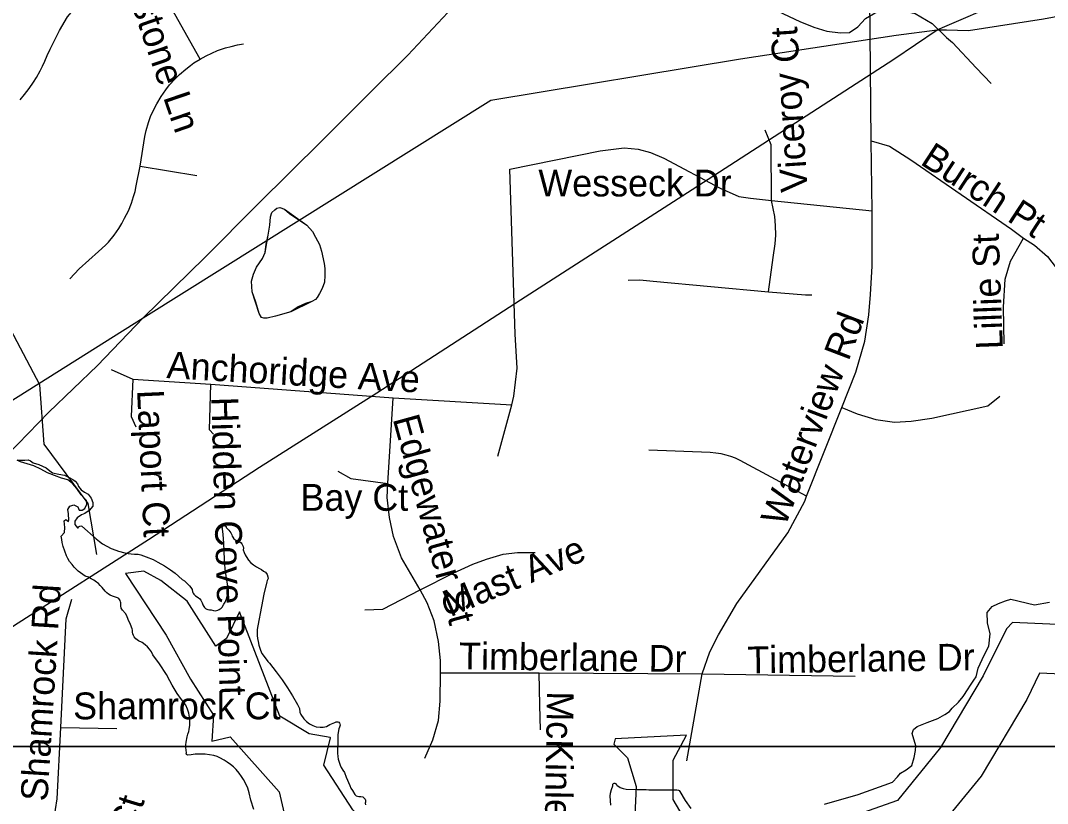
# Model space of a CAD drawing. Extents: x 1662474 to 1856135, y 779280 to 917889.
# Drawn here: x 1701087 to 1704721, y 826386 to 829158 of the extents above; entities that cross this region are included whole.
import ezdxf

# ---------------------------------------------------------------- set-up
doc = ezdxf.new("R2010")
doc.units = 0
for name, color, linetype in [('Exist Hydrographic Lake Shore', 7, 'Continuous'), ('Exist Hydrographic Misc Water Feature', 7, 'Continuous'), ('Exist Road Non-System Type 51', 7, 'Continuous'), ('Exist Road Non-System Type 51 Label', 7, 'Continuous'), ('Exist Utilities Electrical Transmission Line', 7, 'Continuous'), ('Map Preparation Inset Cut Line', 7, 'Continuous'), ('Old_Level_44', 7, 'Continuous')]:
    doc.layers.add(name, color=color, linetype=linetype)

msp = doc.modelspace()

# ---------------------------------------------------------------- linework, layer by layer
at = {"layer": 'Exist Hydrographic Lake Shore'}
for points in [[(1701499.4, 826965.1), (1701494.1, 826969.6), (1701489.2, 826975.8), (1701486.2, 826980.8), (1701484.2, 826987.1), (1701483.1, 826992.6), (1701482.9, 826999.4), (1701481.4, 827004.9), (1701476.1, 827019.4), (1701467.6, 827037.5), (1701462.6, 827050.6), (1701458.2, 827058.8), (1701447.2, 827070.8), (1701443.2, 827077.7), (1701441.1, 827086.6), (1701441.1, 827096.3), (1701440.9, 827100), (1701439.1, 827104.9), (1701437, 827108.6), (1701433.9, 827111.8), (1701429.6, 827114.7), (1701426.2, 827116), (1701419.4, 827117.3), (1701412, 827119.9), (1701404.1, 827123.6), (1701397.6, 827127.8), (1701391.5, 827132.2), (1701386, 827137.5), (1701375.8, 827150.6), (1701368.5, 827158.5), (1701362.1, 827164.6), (1701355.6, 827170.1), (1701346.4, 827176.6), (1701337, 827182.1), (1701327.2, 827187.1), (1701315.5, 827191.6), (1701307.2, 827196.8), (1701291, 827208.9), (1701276.6, 827222.8), (1701269, 827231.8), (1701260.4, 827243.2), (1701254.2, 827253), (1701249, 827263.2), (1701237, 827296.1), (1701234.1, 827309.7), (1701232.8, 827320.9), (1701230.1, 827333.1), (1701241.8, 827345.6), (1701242.8, 827363.5), (1701240.6, 827386.9), (1701247, 827391.3), (1701256.4, 827384.5), (1701257.5, 827388.7), (1701256.4, 827411.5), (1701253.8, 827427), (1701260.6, 827439.1), (1701274.8, 827443), (1701289.5, 827437), (1701294.5, 827424.6), (1701305, 827424.4), (1701314.1, 827430.9), (1701320.8, 827446.2), (1701319.4, 827458.8), (1701300.8, 827479), (1701285.2, 827501), (1701271.1, 827518.1), (1701253.8, 827531.8), (1701231.5, 827538.3), (1701181.4, 827557.4), (1701158, 827570.1), (1701134.1, 827581.9), (1701086.9, 827596.3), (1701075, 827602.1), (1701101.5, 827602.1), (1701113.1, 827603.1), (1701122.2, 827598.9), (1701131.5, 827592.1), (1701151.1, 827586.1), (1701176.9, 827574.5), (1701190.2, 827563.8), (1701200, 827556.9), (1701222.2, 827551.9), (1701242, 827549.1), (1701256.4, 827541.9), (1701271.1, 827533.8), (1701280, 827526.8), (1701287.9, 827517.6), (1701291.9, 827508.6), (1701301, 827497.1), (1701312.9, 827488.9), (1701326, 827481.1), (1701336.1, 827466.6), (1701342, 827452.2), (1701342, 827438.6), (1701329.9, 827423.9), (1701314.1, 827412.6), (1701302.4, 827408.6), (1701286.6, 827398.1), (1701279, 827385.8), (1701279, 827373.8)], [(1701279, 827373.8), (1701287.9, 827362.2), (1701290.2, 827362.7), (1701292.1, 827365.9), (1701293.9, 827367.4), (1701296.2, 827368.5), (1701300, 827368.8), (1701303.6, 827367.7), (1701354, 827323.1), (1701366.1, 827313.4), (1701376.6, 827305.8), (1701407.2, 827288.9), (1701410.8, 827287.4), (1701432.8, 827279.2), (1701455.4, 827273.2), (1701466.9, 827271.4), (1701478.4, 827269.8), (1701490.2, 827269), (1701502.6, 827269), (1701512, 827266.1), (1701530.9, 827259.6), (1701555.4, 827249.6), (1701572.9, 827240.9), (1701596, 827227.8), (1701617.8, 827213.4), (1701633.8, 827201.3), (1701658.5, 827179.8), (1701666.9, 827174.2), (1701675.8, 827164.8), (1701684.8, 827156.7), (1701689.5, 827150.9), (1701693.4, 827144.3), (1701695.2, 827135.9), (1701697.4, 827130.9), (1701699.8, 827127.2), (1701705.2, 827122), (1701715.4, 827115.4), (1701720.6, 827110.8), (1701724.1, 827106.6), (1701727, 827101.8), (1701729.1, 827096.8), (1701731.5, 827089.2), (1701734.9, 827083.2), (1701737.5, 827080), (1701741.1, 827076.9), (1701745.6, 827074), (1701749.2, 827072.7), (1701755.4, 827071.4), (1701761.6, 827071.4), (1701770, 827069), (1701776.4, 827068.8), (1701785, 827070.3), (1701790, 827072.7), (1701796.8, 827077.9), (1701799.8, 827081.1), (1701806.5, 827091.6), (1701810.8, 827098.9), (1701815.8, 827111), (1701819.4, 827125.4), (1701821, 827137), (1701820.6, 827148.5), (1701819.9, 827156.9), (1701815.1, 827184.2), (1701811, 827217.1), (1701808.9, 827249.8), (1701806.5, 827307.6), (1701803.9, 827338.8), (1701801.5, 827358.5), (1701800.2, 827362.4), (1701800.8, 827365.3), (1701801.5, 827367.2), (1701803.9, 827369.2), (1701807.9, 827370.3), (1701811, 827369.5), (1701813.9, 827366.9), (1701814.9, 827362.9), (1701823.6, 827353.8), (1701830.6, 827344.3), (1701834.6, 827337.2), (1701835.9, 827332.8), (1701837.5, 827329.6), (1701841.6, 827323.6), (1701844.6, 827321.2), (1701848.5, 827318.9), (1701852.8, 827317.1), (1701856.6, 827316), (1701862.4, 827313.1), (1701867.1, 827309.2), (1701870.2, 827305.2), (1701872.6, 827300.8), (1701874.5, 827296.1), (1701875.2, 827289.8), (1701874.8, 827283.7), (1701877.9, 827275.1), (1701881.6, 827266.6), (1701885.2, 827260.3), (1701893.6, 827248.2), (1701902.2, 827238.8), (1701910.5, 827231.4), (1701921.2, 827224.1)], [(1701921.2, 827224.1), (1701932.5, 827218.4), (1701939.4, 827214.9), (1701946.6, 827209.2), (1701954, 827204.9), (1701959.2, 827197.1), (1701961.9, 827188.2), (1701962.4, 827182.9), (1701959, 827176.1), (1701958.2, 827171.1), (1701948.2, 827127), (1701939.4, 827083.4), (1701926.5, 827015.4), (1701924.6, 827002.3), (1701924.1, 826991.8), (1701924.4, 826981.1), (1701925.4, 826970.6), (1701927.2, 826960.1), (1701930.1, 826947.2), (1701936.1, 826928.6), (1701941.1, 826917.8), (1701955.6, 826897.1), (1701962.1, 826888.9), (1701968.2, 826882.7), (1701991.8, 826852.5), (1702012, 826824.6), (1702031.5, 826796.1), (1702049.5, 826766.9), (1702066.9, 826737), (1702073.8, 826722.8), (1702075, 826709.7), (1702078.4, 826701.3), (1702088.9, 826686.1), (1702098.1, 826676.4), (1702108.9, 826668.2), (1702120.6, 826662.2), (1702133.2, 826658.2), (1702146.6, 826656.7), (1702157.4, 826656.9), (1702169, 826659.1), (1702181.6, 826665.6), (1702199.1, 826672.7), (1702203.9, 826675.3), (1702206.2, 826675.6), (1702209.6, 826675.1), (1702213.1, 826673.8), (1702215.8, 826671.1), (1702217.2, 826668.2), (1702218, 826663.5), (1702217.2, 826660.1), (1702215.4, 826656.9), (1702213.6, 826650.9), (1702210.1, 826630.9), (1702209.1, 826613.4), (1702209.9, 826595.8), (1702208.4, 826584.5), (1702207.9, 826575.3), (1702208.1, 826564), (1702209.4, 826552.5), (1702211, 826543.6), (1702214.1, 826532.6), (1702218, 826522.1), (1702221.8, 826513.6), (1702227.2, 826503.7), (1702232.8, 826495.5), (1702239, 826479.8), (1702251.9, 826450.4), (1702255, 826440.9), (1702261.9, 826432.6), (1702270.2, 826418.1), (1702274.8, 826413.9), (1702279.2, 826411.8), (1702283.9, 826411), (1702291.2, 826411.2), (1702297.6, 826409.7), (1702301.8, 826406.8), (1702305.8, 826401.8), (1702307.2, 826398.4), (1702307.9, 826394.5), (1702307.9, 826390.8), (1702306.8, 826386.9), (1702307.2, 826381.9)], [(1704190.2, 826480.1), (1704201.2, 826494.2), (1704221.4, 826505.8), (1704241.6, 826520.8), (1704250, 826549.6), (1704254.5, 826574.2), (1704255.2, 826590), (1704241.9, 826634.4), (1704247.4, 826648), (1704259.8, 826658.5), (1704294.9, 826672.7), (1704332.8, 826687.1), (1704357.9, 826701.1), (1704374.1, 826712.1), (1704383.6, 826724.1), (1704406.5, 826744.6), (1704422.8, 826765.1), (1704440.6, 826792.1), (1704446.1, 826802.1), (1704460.2, 826822.3), (1704468.4, 826834.9), (1704476.5, 826865.9), (1704496.8, 826911.2), (1704514.1, 826943.8), (1704518.2, 826986.3), (1704509.1, 827025.9), (1704507.8, 827062.4), (1704525.1, 827084.2), (1704547.6, 827094.8), (1704572.9, 827103.9), (1704591, 827109.2), (1704675.5, 827090), (1704728.2, 827099.2)], [(1701536.1, 826940.9), (1701528, 826948.2), (1701516.5, 826956.4), (1701504.1, 826962.2), (1701499.4, 826965.1)], [(1701912.2, 826364.8), (1701902, 826398.4), (1701896, 826423.9), (1701890.8, 826440.1), (1701884, 826455.9), (1701876.1, 826470.9), (1701868.8, 826482.4), (1701860.6, 826493.4), (1701849.5, 826506.3), (1701839.9, 826516), (1701829.4, 826524.7), (1701818.4, 826533.1), (1701806.8, 826540.1), (1701791.9, 826548.2), (1701782.4, 826552.5), (1701770.5, 826556.7), (1701739.9, 826560.4), (1701705, 826560.4), (1701690.2, 826559.1), (1701678.8, 826557.2), (1701676.6, 826558), (1701674.2, 826560.1), (1701673.1, 826563.2), (1701673.8, 826565.9), (1701671.9, 826584.5), (1701671.9, 826594.2), (1701672.6, 826603.9), (1701676.1, 826622.8), (1701678.8, 826632), (1701682.1, 826641.2), (1701683.6, 826648.2), (1701685.2, 826663), (1701685.5, 826675.1), (1701684.5, 826692.1), (1701681.9, 826706.6), (1701677.4, 826720.4), (1701671.4, 826734.9), (1701655.9, 826754.6), (1701641.4, 826775.1), (1701623, 826804.9), (1701614.6, 826820.7), (1701603.4, 826843.3), (1701578.1, 826880.3), (1701554.8, 826912.1), (1701549.5, 826923.3), (1701543.2, 826932.5), (1701536.1, 826940.9)], [(1703175.5, 826380.6), (1703174, 826412.6), (1703174.5, 826422.8), (1703177.6, 826435.4), (1703183.1, 826448.8), (1703182.4, 826451.9), (1703182.9, 826454.1), (1703185, 826456.7), (1703188.1, 826458), (1703190.2, 826458), (1703192.2, 826456.9), (1703193.9, 826455.6), (1703196, 826452.2), (1703198.1, 826450.1), (1703204.1, 826445.9), (1703209.4, 826442.8), (1703219.1, 826438.8), (1703230.4, 826436.5), (1703269, 826435.7), (1703301, 826436.2), (1703310.1, 826434.9), (1703409.9, 826434.9), (1703414.9, 826433.3), (1703417.2, 826431.8), (1703420.1, 826428.9), (1703439.2, 826397.1), (1703459.2, 826368.2)], [(1703932.2, 826384.2), (1704050.9, 826417.8), (1704172.9, 826461.7), (1704190.2, 826480.1)]]:
    msp.add_lwpolyline(points, dxfattribs=at)
at = {"layer": 'Exist Hydrographic Misc Water Feature'}
for points in [[(1701357, 827267.3), (1701326.1, 827448.5), (1701170, 827658.5), (1701155, 827868.8), (1700959, 828237.2), (1700169, 829178.9), (1700005, 829454.6), (1699824.4, 829654.8)], [(1703219.3, 829651.9), (1703249.2, 829638.2), (1703292.6, 829605.3), (1703373.7, 829540.4), (1703532.2, 829400.2), (1703555.5, 829357.9), (1703590.9, 829311.2), (1703665.9, 829244), (1703767.3, 829191), (1703844.9, 829154.1), (1703894.5, 829135.1), (1703940.2, 829120.2), (1703988.3, 829114.3), (1704020.3, 829115.3), (1704050.5, 829135.2), (1704076.9, 829165), (1704119.4, 829190.5), (1704171.5, 829201.7), (1704253.2, 829182.8), (1704312.7, 829147.9), (1704363.5, 829098.5)], [(1704363.5, 829098.5), (1704385.2, 829080.8), (1704469, 828990.5), (1704522.5, 828935.2)], [(1702099.4, 828433.1), (1702119.7, 828411.3), (1702130.8, 828390.6), (1702144.5, 828364.9), (1702151.7, 828341), (1702161.4, 828298), (1702163.3, 828280), (1702163.1, 828255.4), (1702162.6, 828231.6), (1702154.3, 828209.6), (1702144.2, 828191.7), (1702136.4, 828177.9), (1702130, 828169.9), (1702117.7, 828163.6), (1702095.7, 828156.6), (1702069.6, 828144.8), (1702043.3, 828127.3), (1701989.1, 828112), (1701958.9, 828104.4), (1701947.8, 828103.8), (1701939.1, 828106.4), (1701931.2, 828120.6), (1701919.9, 828161), (1701906.3, 828197.4), (1701904.5, 828235.2), (1701910.7, 828259.7), (1701921.4, 828284.9), (1701942.5, 828315.6), (1701951.9, 828336.8), (1701956.4, 828366.3), (1701962.9, 828398.1), (1701969.3, 828434), (1701971.8, 828462.8), (1701976.4, 828478.2), (1701986, 828487.9), (1701994.2, 828493.5), (1702004.3, 828495.8), (1702020.8, 828490.4), (1702037.9, 828475.4), (1702099.4, 828433.1)], [(1702099.4, 828433.1), (1702119.7, 828411.3), (1702130.8, 828390.6), (1702144.5, 828364.9), (1702151.7, 828341), (1702161.4, 828298), (1702163.3, 828280), (1702163.1, 828255.4), (1702162.6, 828231.6), (1702154.3, 828209.6), (1702144.2, 828191.7), (1702136.4, 828177.9), (1702130, 828169.9), (1702117.7, 828163.6), (1702043.3, 828127.3), (1701989.1, 828112), (1701958.9, 828104.4), (1701947.8, 828103.8), (1701939.1, 828106.4), (1701931.2, 828120.6), (1701906.3, 828197.4), (1701904.5, 828235.2), (1701910.7, 828259.7), (1701921.4, 828284.9), (1701942.5, 828315.6), (1701951.9, 828336.8), (1701962.9, 828398.1), (1701969.3, 828434), (1701971.8, 828462.8), (1701976.4, 828478.2), (1701986, 828487.9), (1701994.2, 828493.5), (1702004.3, 828495.8), (1702020.8, 828490.4), (1702099.4, 828433.1)]]:
    msp.add_lwpolyline(points, dxfattribs=at)
at = {"layer": 'Exist Road Non-System Type 51'}
for p, q in [((1704096.8, 828731.9), (1704091.8, 829315.4)), ((1704100.4, 828484.2), (1704096.8, 828731.9)), ((1701510.4, 828642.2), (1701710.1, 828608.9)), ((1703744.8, 828520.4), (1704100.4, 828484.2)), ((1701407.2, 827922.2), (1701483.4, 827888.2)), ((1701483.4, 827888.2), (1701760.4, 827870.2)), ((1701760.4, 827870.2), (1702405.6, 827822.2)), ((1702386.9, 827518.6), (1702405.6, 827822.2)), ((1702405.6, 827822.2), (1702825.1, 827797.4)), ((1702775.8, 827616.2), (1702825.1, 827797.4)), ((1703868.9, 827474.5), (1703993.6, 827788.2)), ((1702573.1, 826849), (1702922.5, 826848.8)), ((1702922.5, 826848.8), (1703498.9, 826845.4)), ((1703444.8, 826537.2), (1703498.9, 826845.4)), ((1703498.9, 826845.4), (1704041.1, 826837.5)), ((1701229.4, 826655.4), (1701427, 826651.9))]:
    msp.add_line(p, q, dxfattribs=at)
for points in [[(1701722.5, 829021.2), (1701611.8, 829218.6), (1701607.2, 829228.2), (1701593.9, 829252.4), (1701586.9, 829263.9), (1701575, 829281), (1701562.4, 829297.6), (1701549.2, 829313.4), (1701539.9, 829323.2), (1701530.1, 829333), (1701514.9, 829347.2), (1701504.1, 829355.9), (1701488.1, 829368.7), (1701452.4, 829399.7)], [(1701084.8, 828876.9), (1701100.5, 828895.8), (1701117.2, 828917.8), (1701132.8, 828940.4), (1701142.8, 828956.1), (1701156.1, 828980.5), (1701164.5, 828997), (1701172.1, 829013.9), (1701180.8, 829034.6), (1701191, 829056.6), (1701213.4, 829101.2), (1701224.6, 829122.8), (1701252.6, 829171), (1701272.9, 829194.2)], [(1701722.5, 829021.2), (1701744, 829033), (1701764, 829042.4), (1701784.1, 829051.4), (1701797.4, 829056.4), (1701811.5, 829061.1), (1701832.5, 829066.4), (1701854, 829071.6), (1701875.8, 829075)], [(1701510.4, 828642.2), (1701526.1, 828747.9), (1701530.9, 828769.2), (1701539.4, 828797.6), (1701546.9, 828818), (1701555.9, 828838), (1701569, 828863.7), (1701583.9, 828888.7), (1701600.8, 828912.5), (1701613.9, 828929.9), (1701633.5, 828951.1), (1701649, 828966.6), (1701671.1, 828985.5), (1701688.4, 828999.2), (1701699.9, 829007.8), (1701722.5, 829021.2)], [(1703744.8, 828520.4), (1703743.8, 828717.5), (1703722.1, 828770.5)], [(1704096.8, 828731.9), (1704162.6, 828713.1), (1704237.4, 828664.5), (1704593.9, 828419.4), (1704636.4, 828387.1)], [(1702825.1, 827797.4), (1702832.4, 827827.8), (1702844, 827927.8), (1702836.9, 828047.7), (1702818, 828631.4), (1703138, 828696.2), (1703223.5, 828707.2), (1703273.1, 828702.6), (1703316.1, 828691.2), (1703363.4, 828670.5), (1703562.4, 828564.2), (1703628.5, 828534.9), (1703669.8, 828528.9), (1703744.8, 828520.4)], [(1701260.9, 828243.4), (1701294.5, 828279.5), (1701362.5, 828340), (1701386.9, 828362.7), (1701397.8, 828373.6), (1701417.9, 828397.9), (1701433.9, 828421.4), (1701445.6, 828439.9), (1701454.9, 828458.4), (1701468.4, 828484.4), (1701479.2, 828511.2), (1701486.8, 828534.8), (1701491.9, 828552.4), (1701496, 828572.6), (1701510.4, 828642.2)], [(1703733.5, 828198.1), (1703750, 828319.4), (1703756.9, 828367.1), (1703759.5, 828398.4), (1703758.4, 828432.5), (1703755.9, 828464.8), (1703744.8, 828520.4)], [(1703993.6, 827788.2), (1704042.6, 827913.1), (1704075.2, 828022.8), (1704089.1, 828116.2), (1704095.4, 828188.7), (1704100.4, 828288.7), (1704100.4, 828484.2)], [(1704567.6, 828014.1), (1704566.2, 828143.5), (1704571.9, 828243), (1704590.6, 828306), (1704636.4, 828387.1)], [(1704636.4, 828387.1), (1704674.9, 828363.2), (1704721.9, 828322.5), (1704809.4, 828206.8)], [(1703236.6, 828239), (1703277.9, 828239.9), (1703325.1, 828235.9), (1703733.5, 828198.1)], [(1703733.5, 828198.1), (1703864.8, 828186.9), (1703887, 828186.6)], [(1701483.4, 827888.2), (1701478.1, 827755.9), (1701494.6, 827719.4)], [(1701769.8, 827693.4), (1701755.1, 827708.9), (1701760.4, 827870.2)], [(1703993.6, 827788.2), (1704047.9, 827766.1), (1704113.5, 827745.4), (1704180.1, 827735.9), (1704238.5, 827740.1), (1704312.5, 827750.6), (1704510.4, 827794.4), (1704552.1, 827828.6)], [(1703868.9, 827474.5), (1703633, 827601), (1703617.2, 827608.4), (1703600.6, 827614.7), (1703583.9, 827619.7), (1703566.9, 827623.9), (1703547.4, 827627), (1703527.1, 827628.9), (1703310.1, 827636.7)], [(1702209.4, 827563.2), (1702255.4, 827536.9), (1702386.9, 827518.6)], [(1702501.5, 827142.5), (1702434.6, 827255.9), (1702406.8, 827330.9), (1702392.4, 827398.4), (1702383.9, 827469), (1702386.9, 827518.6)], [(1703498.9, 826845.4), (1703526.4, 826923.4), (1703556.6, 826983.4), (1703621.6, 827093.9), (1703801.8, 827344.4), (1703861.9, 827456.4), (1703868.9, 827474.5)], [(1702501.5, 827142.5), (1702617.2, 827201.5), (1702687.4, 827233.6), (1702735.9, 827251.4), (1702794.4, 827269.2), (1702845.4, 827275.2), (1702908.4, 827275)], [(1702305.1, 827071.6), (1702368.6, 827074.5), (1702501.5, 827142.5)], [(1702573.1, 826849), (1702573.1, 826892.9), (1702565.9, 826959.9), (1702550.6, 827033.2), (1702525.6, 827097.1), (1702501.5, 827142.5)], [(1701229.4, 826655.4), (1701248, 827039.6), (1701268.1, 827109.7)], [(1702517.2, 826546.2), (1702546.1, 826611.8), (1702565.9, 826679.5), (1702571.9, 826748), (1702573.1, 826849)], [(1702926.9, 826646.8), (1702924.6, 826734.4), (1702922.5, 826848.8)], [(1701191.2, 826289.8), (1701204.9, 826327), (1701216.2, 826402.6), (1701229.4, 826655.4)]]:
    msp.add_lwpolyline(points, dxfattribs=at)
at = {"layer": 'Exist Utilities Electrical Transmission Line'}
for points in [[(1704330.5, 829125.1), (1704357.7, 829137.4), (1704549.9, 829219.5), (1704987.4, 829509.1), (1705656.6, 829944.3), (1706235.2, 830322.3), (1706743.5, 830657.3), (1707181, 830946.8), (1707763.6, 831326.9), (1708303.7, 831673.4), (1708928.7, 832081.1), (1709620.3, 832536.3), (1710291.6, 832975.4), (1711027.5, 833455.9), (1711648.5, 833863.6), (1712239.1, 834253.8), (1713005.3, 834756), (1713847.9, 835307.5)], [(1704330.5, 829125.1), (1704363.9, 829125.2), (1704441.7, 829122.8), (1704707.5, 829163.8), (1705527.8, 829317.2), (1706167.7, 829434.6), (1706717.3, 829530.9), (1706941.1, 829496.5), (1707139, 829464.5), (1707886.3, 829332.6), (1708789.5, 829173.1), (1709700.6, 829009.5), (1710597.6, 828852.2), (1711504.6, 828682.4), (1712417.9, 828528.9), (1713335, 828365.2)], [(1701520.4, 828105.5), (1701738.8, 828319.2), (1701924.9, 828507.3), (1702155.5, 828734.8), (1702327.5, 828907), (1702457, 829035.6), (1702598.5, 829186.2)], [(1698412.5, 825294.6), (1698803.4, 825554.4), (1700105.2, 826390.5), (1700818.4, 826854.9), (1701078.4, 827026.1), (1701539.9, 827321.1), (1701932.7, 827576.9), (1702347.7, 827840.4), (1702855.5, 828168.9), (1703464, 828560.4), (1704177.3, 829020.8), (1704330.5, 829125.1)], [(1701520.4, 828105.5), (1702751.3, 828876.4), (1703635.2, 829022.8), (1704186.3, 829106.6), (1704330.5, 829125.1)], [(1692929.2, 823686.1), (1695261.2, 824166.9), (1701520.4, 828105.5)], [(1698412.5, 825294.6), (1699147.3, 825882.8), (1699284.5, 825997.3), (1699599.4, 826250), (1700023.5, 826605.4), (1700136.8, 826718.2), (1700328.8, 826908.2), (1700598, 827177.3), (1700966.1, 827545.4), (1701186.6, 827771.1), (1701358.5, 827937.3), (1701520.4, 828105.5)]]:
    msp.add_lwpolyline(points, dxfattribs=at)
at = {"layer": 'Map Preparation Inset Cut Line'}
for points in [[(1731035.7, 826588.1), (1668486.3, 826588.1), (1668486.3, 870408.9), (1731035.7, 870408.9)], [(1731035.7, 782767.4), (1668486.3, 782767.4), (1668486.3, 826588.1), (1731035.7, 826588.1)]]:
    msp.add_lwpolyline(points, close=True, dxfattribs=at)
at = {"layer": 'Old_Level_44'}
for points in [[(1705901.8, 829015.1), (1705894.7, 828930.6), (1705916.2, 828927.9), (1706106.2, 828756), (1706166.5, 828501.8), (1706147, 828268.2), (1706022.5, 828070.5), (1705831, 827949.4), (1705417.3, 827839.9), (1705401.3, 827859.9), (1705238.3, 827705.6), (1705164.3, 827606.9), (1705103.7, 827506.1), (1705250.5, 827304.5), (1705061.4, 827039.9), (1704848.8, 826840.7), (1704693.6, 826847.2), (1704647.9, 826754.4), (1704486.8, 826483.2), (1704294.5, 826248.3)], [(1701861.1, 827065.1), (1701815.9, 826970.7), (1701777.6, 826943.2), (1701676.4, 827102.1), (1701582.6, 827175.8), (1701523.2, 827208.2), (1701458.5, 827201), (1701602, 826981.7), (1701687.5, 826826.3), (1701769.3, 826699.2), (1701763.1, 826607.3), (1701828, 826622.5), (1702002.2, 826427.9), (1702044.3, 826243.1), (1702070.3, 826171.7), (1702153.2, 826055.6), (1702169.2, 825911.6), (1702235.9, 825791.6), (1702327.1, 825685.3), (1702414.3, 825554.6), (1702287.7, 825455.1)], [(1702964.1, 826137.9), (1702860.1, 826096.3), (1702783.8, 826011.7), (1702637.3, 826000.4), (1702530.3, 826087.9), (1702435.7, 826198.2), (1702262.2, 826363.7), (1702159.6, 826522.1), (1702183.8, 826618.7), (1702183, 826620.3), (1702107.9, 826632.8), (1702004.2, 826695), (1701861.1, 827065.1)], [(1704782.6, 827019), (1704597.5, 827026.7), (1704575.9, 827005.1), (1704493.6, 826838), (1704342.8, 826584), (1704190, 826397.4), (1704046, 826346.6)], [(1703471.4, 826272.2), (1703396.7, 826400.2), (1703396.7, 826539.1), (1703444, 826627.7), (1703190.8, 826615.7), (1703186, 826596.7), (1703235.2, 826547.7), (1703265.5, 826446.4), (1703255.9, 826243.3)]]:
    msp.add_lwpolyline(points, dxfattribs=at)

# ---------------------------------------------------------------- texts
at = {"layer": 'Exist Road Non-System Type 51 Label'}
for s, rotation, p in [('Netherstone Ln', 288.8424, (1701355.6, 829575.3)), ('Viceroy Ct', 93.6893, (1703872.7, 828553.2)), ('Burch Pt', 326.8433, (1704267.1, 828651.6)), ('Lillie St', 92.1138, (1704563.7, 827995.5)), ('Waterview Rd', 69.0979, (1703792.7, 827362.9)), ('Anchoridge Ave', 356.6963, (1701601.9, 827892.4)), ('Laport Ct', 272.6011, (1701499, 827849.3)), ('Hidden Cove Point', 271.6356, (1701761.6, 827824.9)), ('Edgewater St', 285.4138, (1702403.1, 827748)), ('Mast Ave', 22.8453, (1702607.2, 827045.3)), ('Shamrock Rd', 86.4257, (1701181.5, 826392.1)), ('Timberlane Dr', 359.2853, (1702638.4, 826861.3)), ('Timberlane Dr', 0.7981, (1703659.3, 826846.7)), ('McKinley St', 269.0765, (1702950, 826784)), ('Northshore Ct', 73.28, (1701299.1, 825639.9))]:
    msp.add_text(s, height=95, rotation=rotation, dxfattribs=at).set_placement(p)
for s, p in [('Wesseck Dr', (1702919.2, 828535.3)), ('Bay Ct', (1702077.5, 827422.4)), ('Shamrock Ct', (1701272.7, 826684.3))]:
    msp.add_text(s, height=95, dxfattribs=at).set_placement(p)

doc.saveas('drawing.dxf')
